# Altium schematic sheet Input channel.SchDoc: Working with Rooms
size 431 x 279 mm; Organization: Altium Limited; Address1: L3, 12a Rodborough Rd; Address2: Frenchs Forest; Address3: NSW; Address4: Australia 2086; DocumentNumber: 4; SheetNumber: 4; SheetTotal: 8
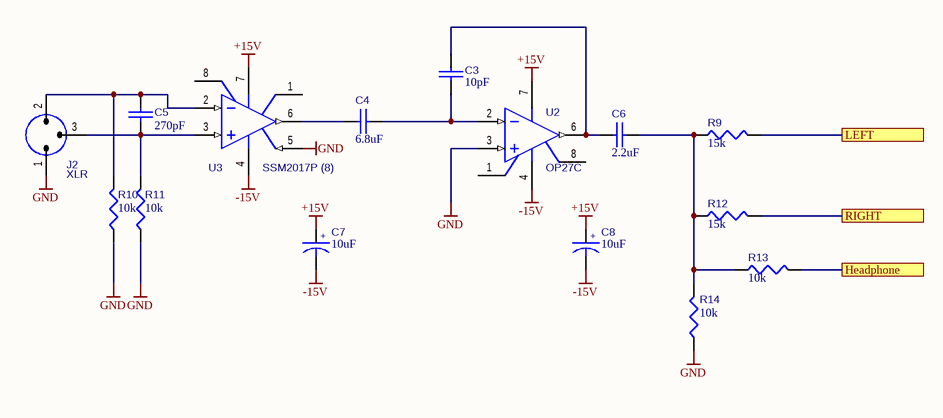
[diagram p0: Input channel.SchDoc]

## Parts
C3  10pF  [RAD0.2]
C4  6.8uF  [RB.2/.4-NP]
C5  270pF  [RAD0.2]
C6  2.2uF  [RB.2/.4-NP]
C7  10uF  [RB.2/.4]
C8  10uF  [RB.2/.4]
J2  XLR  [XLR-FEMALE]
R9  15k  [AXIAL0.4]
R10  10k  [AXIAL0.4]
R11  10k  [AXIAL0.4]
R12  15k  [AXIAL0.4]
R13  10k  [AXIAL0.4]
R14  10k  [AXIAL0.4]
U2  OP27C  [DIP8]
U3  SSM2017P (8)  [DIP8]

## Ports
Headphone, LEFT, RIGHT

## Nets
+15V: C7.1 C8.1 U2.7(V+) U3.7(V+)
-15V: C7.2 C8.2 U2.4(V-) U3.4(V-)
GND: J2.1 R10.1 R11.1 R14.1 U2.3(+IN) U3.5(REF)
Headphone: R13.2 ; port Headphone
LEFT: R9.2 ; port LEFT
RIGHT: R12.2 ; port RIGHT
NetC3_1: C3.1 C4.2 U2.2(-IN)
NetC3_2: C3.2 C6.1 U2.6(OUT)
NetC4_1: C4.1 U3.6(OUT)
NetC5_1: C5.1 J2.2 R10.2 U3.2(IN-)
NetC5_2: C5.2 J2.3 R11.2 U3.3(IN+)
NetC6_2: C6.2 R9.1 R12.1 R13.1 R14.2

Not connected (* = marked no-connect by the designer): U2 1(TRIM) 8(TRIM); U3 1(RG1) 8(RG2)

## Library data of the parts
C3-C6 = CAP: Capacitor
C7 C8 = CAPACITOR POL: Bi-Polar Capacitor
J2 = XLR: XLR connector, PCB mounted
R9-R14 = RES1: Resistor
U2 = OP27C: Low Noise, High Speed Precision Operational Amplifier
U3 = SSM2017P (8): Self-Contained Audio Preamplifier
